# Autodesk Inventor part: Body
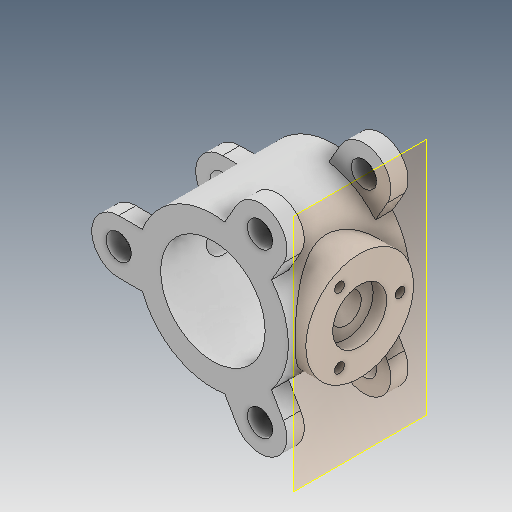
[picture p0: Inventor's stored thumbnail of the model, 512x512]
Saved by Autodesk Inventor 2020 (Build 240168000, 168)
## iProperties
Created: 2019-03
Part Number: Body
Material: Generic
Document SubType Name: Modeling
Designer: LENOVO-CADCIM
Density: 1 g/cm^3
Appearance: Default
Author: LENOVO-CADCIM
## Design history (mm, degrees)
sketch "Sketch1"
  geometry: C1 r 140 at (0, 0); C2 r 97 at (0, 0); 1 further point
  constraints: 2 centre point, 2 coincident
  dimensions: "d0" = 194 diameter of C2; "d1" = 280 diameter of C1
extrude "Extrusion1" new body sketch "Sketch1" stored distance "d2" = 225; taper "d3" = 0 deg
sketch "Sketch2"
  geometry: L1 (0, 0)-(-428, 0); L2 (-130.767, 50)-(-175, 50); L3 (-130.767, -50)-(-175, -50); C1 r 23.5 at (-175, 0); A1 r 175 centre (0, 0) between (-175, 0) and (-175, 0); A2 r 140 centre (0, 0) between (-130.767, 50) and (-130.767, -50) reference; A3 r 50 centre (-175, 0) between (-175, 50) and (-175, -50); 1 further point
  constraints: 6 end point, 6 point on circle, 3 centre point, 3 horizontal, 2 tangent, 1 coincident, 1 point on line, 1 other
  dimensions: "d4" = 350 diameter of A1; "d5" = 50 radius of A3; "d6" = 47 diameter of C1
extrude "Extrusion2" join sketch "Sketch2" distance "d7" = 32; taper "d8" = 0 deg
pattern_circular "Circular Pattern1" dims angle "d10" = 360 deg
mirror "Mirror1"
workplane "Work Plane1"
sketch "Sketch3"
  geometry: C1 r 100 at (0, 0); 1 further point
  constraints: 1 centre point, 1 coincident
  dimensions: "d13" = 200 diameter of C1
extrude "Extrusion3" join sketch "Sketch3" stored distance "d14" = 32; taper "d15" = 0 deg
sketch "Sketch4" dims "d16" = 150
  geometry: L1 (0, 0)-(102, 0); 2 further points
  constraints: 2 end point, 1 coincident, 1 horizontal, 1 horizontal alignment, 1 point on line, 2 other
hole "Hole1" sketch "Sketch4" at (75, 0) diameter "d17" = 18.376; stored, may be unused: countersink angle "d21" = 90 deg, drill point angle "d23" = 118 deg; dims "d18" = 40, "d19" = 4, "d20" = 2, "d22" = 47.3
pattern_circular "Circular Pattern2" dims angle "d25" = 360 deg
sketch "Sketch5"
  geometry: C1 r 100 at (0, 0) reference; 2 further points
  constraints: 1 coincident
hole "Hole2" sketch "Sketch5" at (0, 0) diameter "d27" = 56; stored, may be unused: countersink angle "d31" = 90 deg, drill point angle "d33" = 118 deg; dims "d28" = 6, "d29" = 100, "d30" = 25, "d32" = 310
body "Solid1"
